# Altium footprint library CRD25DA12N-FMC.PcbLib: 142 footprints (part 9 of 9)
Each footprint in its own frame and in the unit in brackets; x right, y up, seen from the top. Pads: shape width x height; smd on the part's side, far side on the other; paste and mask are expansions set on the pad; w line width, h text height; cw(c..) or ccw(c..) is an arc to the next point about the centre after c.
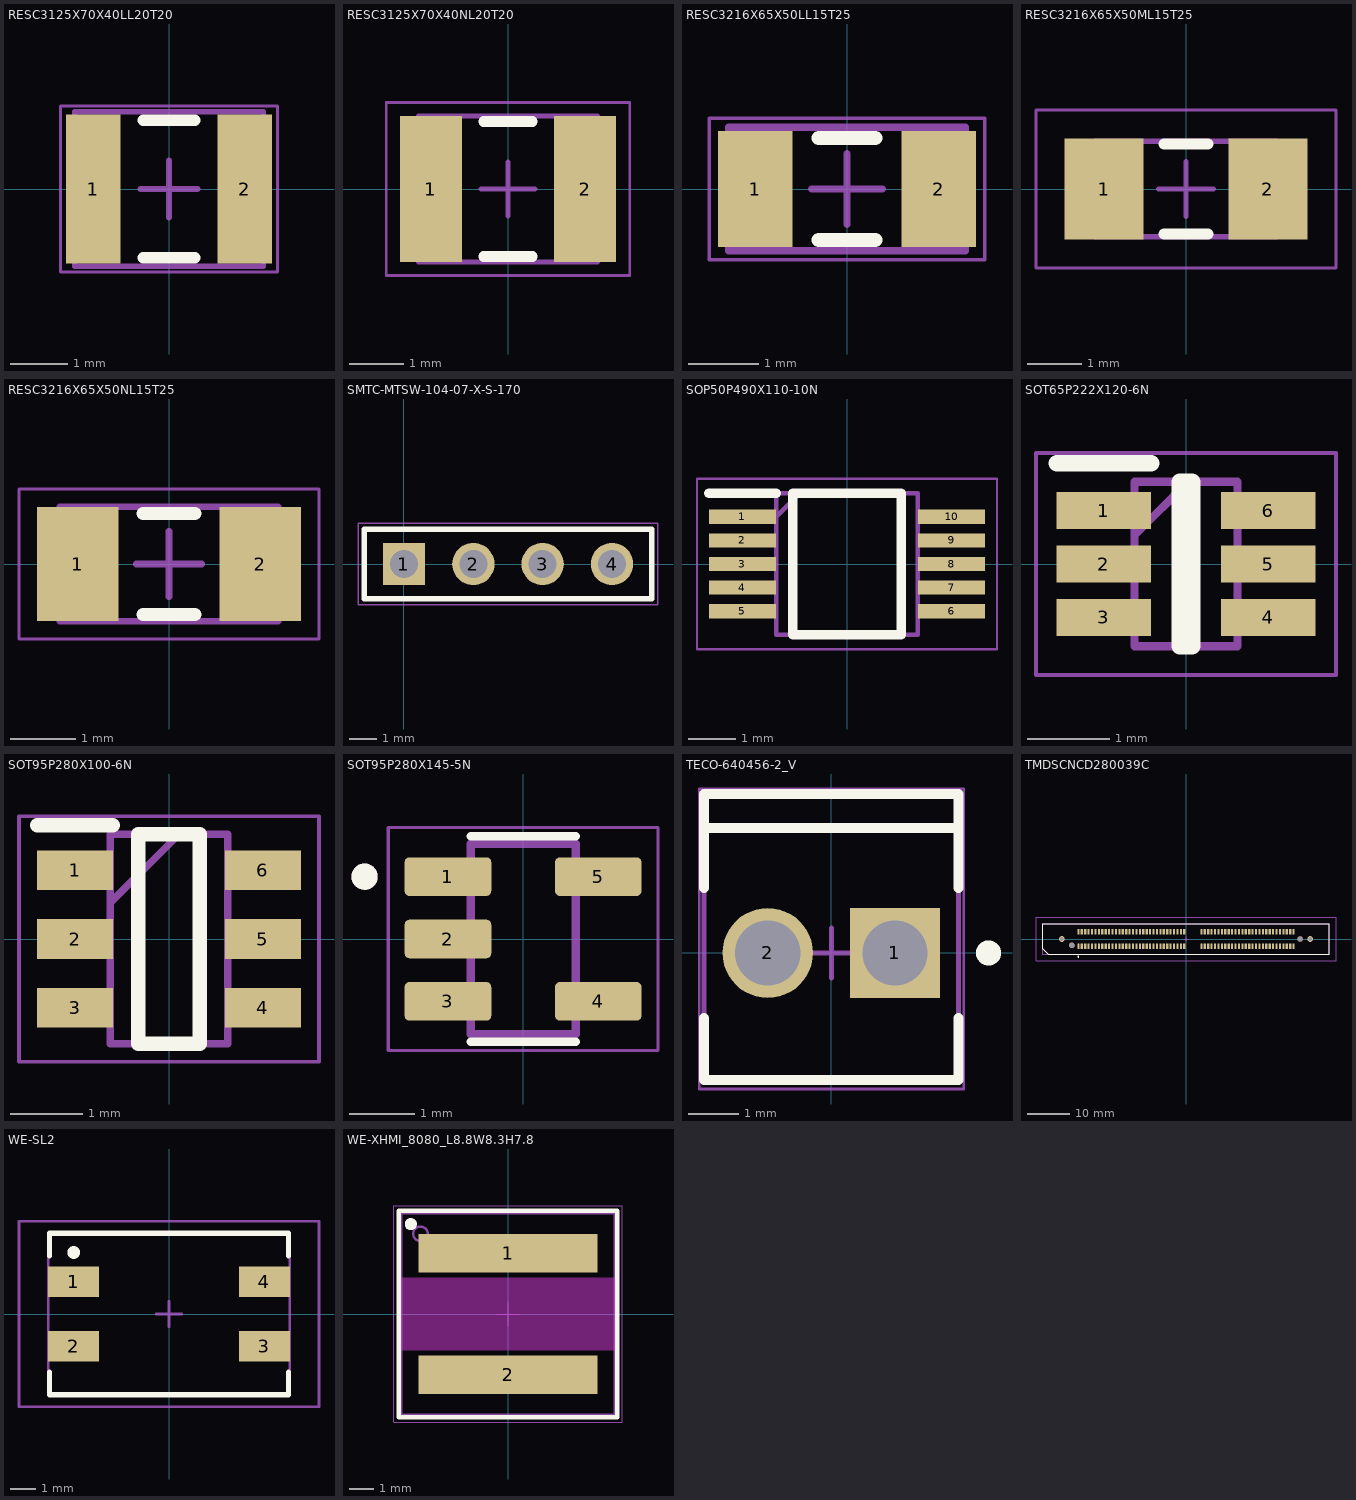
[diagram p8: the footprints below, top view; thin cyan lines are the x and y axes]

## RESC3125X70X40LL20T20 [mm] "Chip Resistor, 2-Leads, Body 3.10x2.50mm, IPC High Density"
height 0.7
pads (2):
  rect 0.95x2.6 smd: 1(-1.325,0) 2(1.325,0)
Top Overlay:
  lines w0.2: -0.45,-1.2 0.45,-1.2 ; -0.45,1.2 0.45,1.2
Mechanical 13:
  lines w0.1: -1.65,-1.35 1.65,-1.35 1.65,1.35 -1.65,1.35 -1.65,-1.35
Mechanical 15:
  lines w0.05: -1.9,-1.45 1.9,-1.45 1.9,1.45 -1.9,1.45 -1.9,-1.45
  lines w0.1: -0.5,0 0.5,0 ; 0,-0.5 0,0.5
3D body: height 0.7, standoff 0, extent 1.25,-1.35 1.65,1.35
3D body: height 0.7, standoff 0, extent -1.65,-1.35 -1.25,1.35
3D body: height 0.7, standoff 0, extent -1.25,-1.35 1.25,1.35

## RESC3125X70X40NL20T20 [mm] "Chip Resistor, 2-Leads, Body 3.10x2.50mm, IPC Medium Density"
height 0.7
pads (2):
  rect 1.15x2.7 smd: 1(-1.425,0) 2(1.425,0)
Top Overlay:
  lines w0.2: -0.45,-1.25 0.45,-1.25 ; -0.45,1.25 0.45,1.25
Mechanical 13:
  lines w0.1: -1.65,-1.35 -1.65,1.35 1.65,1.35 1.65,-1.35 -1.65,-1.35
Mechanical 15:
  lines w0.05: -2.25,-1.6 -2.25,1.6 2.25,1.6 2.25,-1.6 -2.25,-1.6
  lines w0.1: -0.5,0 0.5,0 ; 0,-0.5 0,0.5
3D body: height 0.7, standoff 0, extent -1.25,-1.35 1.25,1.35
3D body: height 0.7, standoff 0, extent -1.65,-1.35 -1.25,1.35
3D body: height 0.7, standoff 0, extent 1.25,-1.35 1.65,1.35

## RESC3216X65X50LL15T25 [mm] "Chip Resistor, 2-Leads, Body 3.20x1.60mm, IPC High Density"
height 0.65
pads (2):
  rect 1.05x1.65 smd: 1(-1.3,0) 2(1.3,0)
Top Overlay:
  lines w0.2: -0.4,-0.725 0.4,-0.725 ; -0.4,0.725 0.4,0.725
Mechanical 13:
  lines w0.1: -1.675,-0.875 -1.675,0.875 1.675,0.875 1.675,-0.875 -1.675,-0.875
Mechanical 15:
  lines w0.05: -1.95,-1 -1.95,1 1.95,1 1.95,-1 -1.95,-1
  lines w0.1: -0.5,0 0.5,0 ; 0,-0.5 0,0.5
3D body: height 0.65, standoff 0, extent -1.175,-0.875 1.175,0.875
3D body: height 0.65, standoff 0, extent -1.675,-0.875 -1.175,0.875
3D body: height 0.65, standoff 0, extent 1.175,-0.875 1.675,0.875

## RESC3216X65X50ML15T25 [mm] "Chip Resistor, 2-Leads, Body 3.20x1.60mm, IPC Low Density"
height 0.65
pads (2):
  rect 1.45x1.85 smd: 1(-1.5,0) 2(1.5,0)
Top Overlay:
  lines w0.2: -0.4,-0.825 0.4,-0.825 ; -0.4,0.825 0.4,0.825
Mechanical 13:
  lines w0.1: -1.675,-0.875 -1.675,0.875 1.675,0.875 1.675,-0.875 -1.675,-0.875
Mechanical 15:
  lines w0.05: -2.75,-1.45 -2.75,1.45 2.75,1.45 2.75,-1.45 -2.75,-1.45
  lines w0.1: -0.5,0 0.5,0 ; 0,-0.5 0,0.5
3D body: height 0.65, standoff 0, extent -1.175,-0.875 1.175,0.875
3D body: height 0.65, standoff 0, extent -1.675,-0.875 -1.175,0.875
3D body: height 0.65, standoff 0, extent 1.175,-0.875 1.675,0.875

## RESC3216X65X50NL15T25 [mm] "Chip Resistor, 2-Leads, Body 3.20x1.60mm, IPC Medium Density"
height 0.65
pads (2):
  rect 1.25x1.75 smd: 1(-1.4,0) 2(1.4,0)
Top Overlay:
  lines w0.2: -0.4,-0.775 0.4,-0.775 ; -0.4,0.775 0.4,0.775
Mechanical 13:
  lines w0.1: -1.675,-0.875 1.675,-0.875 1.675,0.875 -1.675,0.875 -1.675,-0.875
Mechanical 15:
  lines w0.05: -2.3,-1.15 2.3,-1.15 2.3,1.15 -2.3,1.15 -2.3,-1.15
  lines w0.1: -0.5,0 0.5,0 ; 0,-0.5 0,0.5
3D body: height 0.65, standoff 0, extent 1.175,-0.875 1.675,0.875
3D body: height 0.65, standoff 0, extent -1.675,-0.875 -1.175,0.875
3D body: height 0.65, standoff 0, extent -1.175,-0.875 1.175,0.875

## SMTC-MTSW-104-07-X-S-170 [mm] "Assembly .025\" [.64] SQ Post Terminal Strip, 1x4 Pins, Vertical, 2.54mm Pitch, Male"
height 7.061
pads (4):
  rect 1.55x1.55 hole 1.02: 1(0,0)
  round 1.55 hole 1.02: 2(2.54,0) 3(5.08,0) 4(7.62,0)
Top Overlay:
  lines w0.2: -1.46,-1.27 -1.46,1.27 9.08,1.27 9.08,-1.27 -1.46,-1.27
Mechanical 13:
  lines w0.1: -1.46,-1.27 -1.46,1.27 9.08,1.27 9.08,-1.27 -1.46,-1.27
Mechanical 15:
  lines w0.05: -1.685,-1.495 -1.685,1.495 9.305,1.495 9.305,-1.495 -1.685,-1.495
3D body "MTSW-104-07-X-S-170.step": height 6.86, standoff -4.06, extent -1.27,-1.27 8.89,1.27

## SOP50P490X110-10N [mm]
pads (10):
  rect 1.425x0.3 smd: 1(-2.212,1) 2(-2.212,0.5) 3(-2.212,0) 4(-2.212,-0.5) 5(-2.212,-1) 6(2.212,-1) 7(2.212,-0.5) 8(2.212,0) 9(2.212,0.5) 10(2.212,1)
Top Overlay:
  lines w0.2: -2.925,1.5 -1.5,1.5 ; -1.15,-1.5 1.15,-1.5 1.15,1.5 -1.15,1.5 -1.15,-1.5
Top Designator:
  text ".Designator" at -7.618,-0.508 h1.52
Mechanical 13:
  lines w0.1: -1.5,1 -1,1.5 ; -1.5,-1.5 1.5,-1.5 1.5,1.5 -1.5,1.5 -1.5,-1.5
Mechanical 15:
  lines w0.05: -3.175,-1.801 3.175,-1.801 3.175,1.801 -3.175,1.801 -3.175,-1.801
3D body "LTC4368IMS-2#PBF.stp": height 1.1, standoff 0, extent -2.45,-1.5 2.45,1.5

## SOT65P222X120-6N [mm]
pads (6):
  rect 1.15x0.45 smd: 1(-1,0.65) 2(-1,0) 3(-1,-0.65) 4(1,-0.65) 5(1,0) 6(1,0.65)
Top Overlay:
  lines w0.2: -1.575,1.225 -0.425,1.225 ; -0.075,-1 0.075,-1 0.075,1 -0.075,1 -0.075,-1
Top Designator:
  text ".Designator" at -7.618,-0.508 h1.52
Mechanical 13:
  lines w0.1: -0.625,0.35 0.025,1 ; -0.625,-1 0.625,-1 0.625,1 -0.625,1 -0.625,-1
Mechanical 15:
  lines w0.05: -1.825,-1.35 1.825,-1.35 1.825,1.35 -1.825,1.35 -1.825,-1.35
3D body "BAS40DW-04-TP.stp": height 1.2, standoff 0, extent -1.112,-1 1.112,1

## SOT95P280X100-6N [mm]
pads (6):
  rect 1.05x0.55 smd: 1(-1.3,0.95) 2(-1.3,0) 3(-1.3,-0.95) 4(1.3,-0.95) 5(1.3,0) 6(1.3,0.95)
Top Overlay:
  lines w0.2: -1.825,1.575 -0.775,1.575 ; -0.425,-1.45 -0.425,1.45 0.425,1.45 0.425,-1.45 -0.425,-1.45
Mechanical 13:
  lines w0.1: -0.812,0.5 0.138,1.45 ; -0.812,-1.45 -0.812,1.45 0.812,1.45 0.812,-1.45 -0.812,-1.45
Mechanical 15:
  lines w0.05: -2.075,-1.7 -2.075,1.7 2.075,1.7 2.075,-1.7 -2.075,-1.7
3D body "LTC6992CS6-2#TRMPBF.stp": height 1, standoff 0, extent -1.4,-1.45 1.4,1.45

## SOT95P280X145-5N [mm]
pads (5):
  rrect25% 1.32x0.59 smd: 1(-1.145,0.95) 2(-1.145,0) 3(-1.145,-0.95) 4(1.145,-0.95) 5(1.145,0.95)
Top Overlay:
  circle w0.2: c-2.415,0.95 r0.1
  lines w0.127: -0.8,-1.565 0.8,-1.565 ; -0.8,1.565 0.8,1.565
Mechanical 13:
  circle w0.2: c-2.415,0.95 r0.1
  lines w0.127: -0.8,-1.45 0.8,-1.45 0.8,1.45 -0.8,1.45 -0.8,-1.45
Mechanical 15:
  lines w0.05: -2.055,-1.7 2.055,-1.7 2.055,1.7 -2.055,1.7 -2.055,-1.7
3D body "SOT-23-5.step": height 1.11, standoff 0.01, extent -1.25,-1.5 1.25,1.5

## TECO-640456-2_V [mm] "HDR, 2-Leads, Body 5.715x5.08mm, Pitch 2.54mm"
height 10.49
pads (2):
  rect 1.8x1.8 hole 1.3: 1(1.27,0)
  round 1.8 hole 1.3: 2(-1.27,0)
Top Overlay:
  circle w0.25: c3.14,0 r0.125
  lines w0.2: -2.54,-1.3 -2.54,-2.54 2.54,-2.54 2.54,-1.3 ; -2.54,1.3 -2.54,3.175 2.54,3.175 2.54,1.3 ; -2.54,2.5 2.54,2.5
Mechanical 13:
  lines w0.1: -2.54,-2.54 -2.54,3.175 2.54,3.175 2.54,-2.54 -2.54,-2.54
Mechanical 15:
  lines w0.05: -2.64,-2.717 2.64,-2.717 2.64,3.275 -2.64,3.275 -2.64,-2.717
  lines w0.1: -0.5,0 0.5,0 ; 0,-0.5 0,0.5
3D body "TE 640456-2 Color.STEP": height 10.09, standoff -3.5, extent -2.54,-2.667 2.54,3.175

## TMDSCNCD280039C [mm]
pads (124):
  rect 0.5x1.2 smd paste+0 mask+0: 1(25.2,1.7) 2(25.2,-1.7) 3(24.4,1.7) 4(24.4,-1.7) 5(23.6,1.7) 6(23.6,-1.7) 7(22.8,1.7) 8(22.8,-1.7) 9(22,1.7) 10(22,-1.7) 11(21.2,1.7) 12(21.2,-1.7) 13(20.4,1.7) 14(20.4,-1.7) 15(19.6,1.7) 16(19.6,-1.7) 17(18.8,1.7) 18(18.8,-1.7) 19(18,1.7) 20(18,-1.7) 21(17.2,1.7) 22(17.2,-1.7) 23(16.4,1.7) 24(16.4,-1.7) 25(15.6,1.7) 26(15.6,-1.7) 27(14.8,1.7) 28(14.8,-1.7) 29(14,1.7) 30(14,-1.7) 31(13.2,1.7) 32(13.2,-1.7) 33(12.4,1.7) 34(12.4,-1.7) 35(11.6,1.7) 36(11.6,-1.7) 37(10.8,1.7) 38(10.8,-1.7) 39(10,1.7) 40(10,-1.7) 41(9.2,1.7) 42(9.2,-1.7) 43(8.4,1.7) 44(8.4,-1.7) 45(7.6,1.7) 46(7.6,-1.7) 47(6.8,1.7) 48(6.8,-1.7) 49(6,1.7) 50(6,-1.7) 51(5.2,1.7) 52(5.2,-1.7) 53(4.4,1.7) 54(4.4,-1.7) 55(3.6,1.7) 56(3.6,-1.7) 57(-0.4,1.7) 58(-0.4,-1.7) 59(-1.2,1.7) 60(-1.2,-1.7) 61(-2,1.7) 62(-2,-1.7) 63(-2.8,1.7) 64(-2.8,-1.7) 65(-3.6,1.7) 66(-3.6,-1.7) 67(-4.4,1.7) 68(-4.4,-1.7) 69(-5.2,1.7) 70(-5.2,-1.7) 71(-6,1.7) 72(-6,-1.7) 73(-6.8,1.7) 74(-6.8,-1.7) 75(-7.6,1.7) 76(-7.6,-1.7) 77(-8.4,1.7) 78(-8.4,-1.7) 79(-9.2,1.7) 80(-9.2,-1.7) 81(-10,1.7) 82(-10,-1.7) 83(-10.8,1.7) 84(-10.8,-1.7) 85(-11.6,1.7) 86(-11.6,-1.7) 87(-12.4,1.7) 88(-12.4,-1.7) 89(-13.2,1.7) 90(-13.2,-1.7) 91(-14,1.7) 92(-14,-1.7) 93(-14.8,1.7) 94(-14.8,-1.7) 95(-15.6,1.7) 96(-15.6,-1.7) 97(-16.4,1.7) 98(-16.4,-1.7) 99(-17.2,1.7) 100(-17.2,-1.7) 101(-18,1.7) 102(-18,-1.7) 103(-18.8,1.7) 104(-18.8,-1.7) 105(-19.6,1.7) 106(-19.6,-1.7) 107(-20.4,1.7) 108(-20.4,-1.7) 109(-21.2,1.7) 110(-21.2,-1.7) 111(-22,1.7) 112(-22,-1.7) 113(-22.8,1.7) 114(-22.8,-1.7) 115(-23.6,1.7) 116(-23.6,-1.7) 117(-24.4,1.7) 118(-24.4,-1.7) 119(-25.2,1.7) 120(-25.2,-1.7)
  round 1.34 hole 0.84 paste-2539.97 mask+0: 121(-29.05,0) 122(29.05,0)
  round 1.27 hole 1.27 unplated paste-2539.97 mask+0: ""(-26.7,-1.5) ""(26.7,0)
Top Overlay:
  circle w0.25: c-25.2,-4.125 r0.125
  lines w0.2: -33.55,-2.295 -33.55,3.565 33.55,3.565 33.55,-3.565 -32.28,-3.565 -33.55,-2.295
Top Paste:
  circle w1.27: c-29.05,0 r0.635
  circle w1.27: c29.05,0 r0.635
Mechanical 5:
  lines w0.2: -35.115,-5.09 35.115,-5.09 35.115,5.09 -35.115,5.09 -35.115,-5.09
  text ".Designator" at 0,0.188 h1
Mechanical 13:
  lines w0.2: -33.55,-3.565 33.55,-3.565 33.55,3.565 -33.55,3.565 -33.55,-3.565
Mechanical 15:
  lines w0.2: -35.115,-5.09 35.115,-5.09 35.115,5.09 -35.115,5.09 -35.115,-5.09
Mechanical 16:
  lines w0.1: -0.5,0 0.5,0 ; 0,-0.5 0,0.5
3D body "TI TMS320F280039C.step": height 57.35, standoff 2, extent -33.874,-4.89 34.671,5.68
3D body "Samtec HSEC8-160-01-L-DV-A-BL.stp": height 12.4, standoff -1.3, extent -33.525,-3.5 33.525,3.5

## WE-SL2 [mm] "SMD Inductor, 4-Leads, Body 6.3 x 9.5 mm"
height 5.3
pads (4):
  rect 2x1.2 smd: 1(-3.75,1.27) 2(-3.75,-1.27) 3(3.75,-1.27) 4(3.75,1.27)
Top Overlay:
  circle w0.25: c-3.75,2.42 r0.125
  lines w0.2: -4.699,-2.286 -4.699,-3.175 ; -4.699,2.286 -4.699,3.175 4.699,3.175 4.699,2.286 ; 4.699,-2.286 4.699,-3.175 ; -4.699,-3.175 4.699,-3.175 ; -4.699,-3.175 4.699,-3.175 ; -4.699,-3.175 4.699,-3.175
Mechanical 13:
  lines w0.1: -4.75,-3.15 4.75,-3.15 4.75,3.15 -4.75,3.15 -4.75,-3.15
Mechanical 15:
  lines w0.1: -0.5,0 0.5,0 ; 0,-0.5 0,0.5 ; -5.9,-3.65 5.9,-3.65 5.9,3.65 -5.9,3.65 -5.9,-3.65
3D body "744229.stp": height 5, standoff 0, extent -4.6,-3 4.6,3

## WE-XHMI_8080_L8.8W8.3H7.8 [mm] "SMT Power Inductor, 2-Leads, body 8.8x8.3mm"
height 7.8
pads (2):
  rect 7.35x1.6 smd: 1(0,2.5) 2(0,-2.5)
Top Layer keep-out:
  region: -4.4,1.5 4.4,1.5 4.4,-1.5 -4.4,-1.5
Top Overlay:
  circle w0.25: c-4,3.7 r0.125
  lines w0.2: -4.5,-4.25 -4.5,4.25 4.5,4.25 4.5,-4.25 -4.5,-4.25
Top 3D Body:
  circle w0.1: c-3.6,3.3 r0.3
  lines w0.1: -4.4,-4.15 4.4,-4.15 4.4,4.15 -4.4,4.15 -4.4,-4.15
Top Courtyard:
  lines w0.05: -0.5,0 0.5,0 ; 0,-0.5 0,0.5 ; -4.7,-4.45 -4.7,4.45 4.7,4.45 4.7,-4.45 -4.7,-4.45
Top Component Outline:
  circle w0.1: c-3.6,3.3 r0.3
  lines w0.1: -4.4,-4.15 -4.4,4.15 4.4,4.15 4.4,-4.15 -4.4,-4.15
Top Designator:
  text ".Designator" at -7.498,-0.5 h1.5
3D body "74439358xxx.stp": height 7.8, standoff 0, extent -4.4,-4.15 4.4,4.15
